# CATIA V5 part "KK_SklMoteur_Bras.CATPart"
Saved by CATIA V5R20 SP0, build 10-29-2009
Part number: skl moteur bras
Bounding box of the stored display mesh (mm): x 900 to 900, y -25 to 25, z -350 to -110
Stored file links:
  G:\Khaled_CFAO_2011\ST2M\ST2M_GR2\tcorbin\Khaled\CAD_ThinkMOTION\KK_SklMoteur_Bras.CATPart
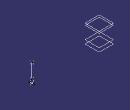
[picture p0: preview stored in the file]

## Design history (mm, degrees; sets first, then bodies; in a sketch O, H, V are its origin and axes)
Set1
  Plane1 "plan extrusion tige": type Offset, RefPlane xy-plane, Offset 135, reversed
  Plane2 "plan extrusion moteur": type Offset, RefPlane xy-plane, Offset 300, reversed
  Point1 "point axe moteur": type OnPlane, Support Plane2, H 900, V 0, Direction (1, 0, 0)
  Plane3 "Plan fin tige": type Offset, RefPlane xy-plane, Offset 110, reversed
  Point2 "point fin tige": type OnPlane, Support Plane3, H 900, V 0, Direction (1, 0, 0)
  Line1 "droite axe moteur bras": type PtPt, FirstPoint Point1, SecondPoint Point2
  Plane4 "plan extrusion raccord": type Offset, RefPlane xy-plane, Offset 350, reversed
  Point3 "centre perçage": type OnPlane, Support Plane4, H 900, V 0, Direction (1, 0, 0)
  Line2 "axe perçage": type PtDir, RefPoint Point3, Direction zx-plane, Start -25, End 25
Body1 (main body)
